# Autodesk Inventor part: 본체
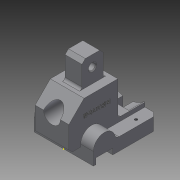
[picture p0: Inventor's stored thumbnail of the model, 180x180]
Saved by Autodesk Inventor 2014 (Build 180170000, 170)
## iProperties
Created: 2016-11
Part Number: 본체
Material: 일반
Document SubType Name: Modeling
Designer: USER
Density: 1 g/cm^3
Appearance: 기본값
Author: USER
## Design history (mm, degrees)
sketch "스케치2"
  geometry: L1 (0, 0)-(3, 0); L2 (3, 0)-(3, 7); L3 (3, 7)-(23, 7); L4 (23, 7)-(23, 0); L5 (23, 0)-(76, 0); L6 (76, 15)-(0, 15); L7 (76, 0)-(76, 15); L8 (13, 7)-(13, 15); L9 (0, 15)-(0, 0); A1 r 13 centre (13, 15) between (26, 15) and (0, 15)
  constraints: 18 end point, 4 parallel, 3 perpendicular, 2 point on circle, 2 point on line, 1 centre point, 1 coincident, 1 horizontal, 1 horizontal alignment, 1 midpoint, 1 tangent
  dimensions: "d9" = 20 distance between parallel lines of L4 L2; "d10" = 7 distance between parallel lines of L1 L3; "d11" = 15 distance between parallel lines of L1 L6; "d13" = 26 diameter of A1; "d14" = 76 distance between parallel lines of L9 L7
extrude "돌출1" new body sketch "스케치2" distance "d15" = 15; taper "d16" = 0 deg
node "작업 평면6"
  node "작업 평면5"
sketch "스케치5"
  geometry: 1 further point
sketch "스케치6"
  geometry: L1 (-60, -14)-(-12, -14); L2 (-12, -14)-(-12, 44); L3 (-12, 44)-(-60, 44); L4 (-60, 44)-(-60, -14); L5 (0, 76)-(-15, 76) reference; L6 (0, 0)-(0, 3) reference
  constraints: 8 end point, 2 parallel, 1 horizontal, 1 perpendicular
  dimensions: "d28" = 90 distance between parallel lines of L5 L1; "d29" = 60 distance between parallel lines of L4 L6; "d30" = 58 distance of L3.end L1.start; "d31" = 48 distance of L1.start L1.end
extrude "돌출3" join sketch "스케치6" stored distance "d32" = 40; taper "d33" = 0 deg
fillet "모깎기1" dims "d34" = 5
sketch "스케치7"
  geometry: L1 (0, 0)-(40, 0) reference; L2 (40, 60)-(55, 60) reference; C1 r 14.5 at (20, 18); 1 further point
  constraints: 1 centre point, 1 midpoint, 1 vertical alignment
  dimensions: "d35" = 42 distance from line of L2 C1.centre; "d36" = 29 diameter of C1
extrude "돌출4" cut sketch "스케치7" distance "d37" = 7; taper "d38" = 0 deg
sketch "스케치8"
  geometry: C1 r 14.5 at (0, 0) reference; C2 r 10 at (0, 0); 1 further point
  constraints: 1 centre point, 1 coincident
  dimensions: "d39" = 20 diameter of C2
extrude "돌출5" cut sketch "스케치8" stored distance "d40" = 7; taper "d41" = 0 deg
chamfer "모따기1" distance "d42" = 1; stored, may be unused: second distance "d43" = 2, angle "d44" = 45 deg
sketch "스케치9"
  geometry: L1 (-60, 44)-(-60, -14) reference; L2 (-60, -14)-(-12, -14) reference; L3 (-42, -14)-(-60, -14); L4 (-60, 4)-(-60, -14); L5 (-60, 4)-(-42, -14); 1 further point
  constraints: 6 end point, 2 collinear, 2 point on line
  dimensions: "d45" = 45 deg angle of L1 L5; "d46" = 18 distance from line of L4.start L2
extrude "돌출6" cut sketch "스케치9" stored distance "d47" = 7; taper "d48" = 0 deg
chamfer "모따기2" distance "d49" = 4; stored, may be unused: second distance "d50" = 2, angle "d51" = 45 deg
chamfer "모따기3" distance "d52" = 5; stored, may be unused: second distance "d53" = 2, angle "d54" = 45 deg
node "작업 평면9"
sketch "스케치13"
  geometry: L1 (-55, 0)-(-55, 15) reference; L2 (-40, 0)-(-40, 15) reference; L3 (-40, 15)-(-55, 15) reference; L4 (-40, 0)-(-55, 0) reference; L5 (15, 15)-(0, 15) reference; L6 (0, 0)-(0, 15) reference; L7 (15, 15)-(15, 0) reference; L8 (0, 0)-(15, 0) reference; L9 (15, 15)-(-55, 15); L10 (-55, 15)-(-55, 0); L11 (-55, 0)-(15, 0); L12 (15, 0)-(15, 15)
  constraints: 8 end point, 2 parallel, 1 horizontal, 1 perpendicular
extrude "돌출8" join sketch "스케치13" distance "d59" = 3; taper "d60" = 0 deg
sketch "스케치16"
  geometry: L1 (0, -5)-(-40, -5); L2 (-40, -5)-(-40, 15); L3 (-40, 15)-(0, 15); L4 (0, 15)-(0, -5); L5 (-55, 15)-(15, 15) reference; 3 further points
  constraints: 8 end point, 3 midpoint, 2 parallel, 1 coincident, 1 horizontal, 1 perpendicular, 1 vertical alignment
  dimensions: "d63" = 20 distance between parallel lines of L3 L1; "d64" = 40 distance of L1.start L1.end
extrude "돌출10" join sketch "스케치16" stored distance "d65" = 18; taper "d66" = 0 deg
sketch "스케치17"
  geometry: L1 (50, -20)-(10, -20) reference; C1 r 14.5 at (30, -42) reference; A1 r 29 centre (30, -42) between (48.894, -20) and (11.106, -20); 1 further point
  constraints: 2 point on circle, 2 point on line, 1 centre point, 1 coincident
  dimensions: "d67" = 58 diameter of A1
extrude "돌출11" cut sketch "스케치17" distance "d68" = 18; taper "d69" = 0 deg
sketch "스케치18"
  geometry: L1 (50, -20)-(48.894, -20) reference; L2 (0, 0)-(60, 0) reference; L3 (11.106, -20)-(10, -20) reference; L4 (36, -13.627)-(36, 0); L5 (24, -13.627)-(24, 0); L6 (36, 0)-(24, 0); A1 r 29 centre (30, -42) between (48.894, -20) and (11.106, -20) reference; A2 r 29 centre (30, -42) between (36, -13.627) and (24, -13.627); 2 further points
  constraints: 8 end point, 4 point on circle, 2 perpendicular, 2 point on line, 1 centre point, 1 coincident, 1 collinear, 1 concentric, 1 midpoint, 1 vertical alignment
  dimensions: "d70" = 12 distance between parallel lines of L5 L4
extrude "돌출12" cut sketch "스케치18" stored distance "d71" = 18; taper "d72" = 0 deg
fillet "모깎기2" dims "d73" = 3
node "작업 평면10"
sketch "스케치20"
  geometry: L1 (45, -11.5)-(25, -11.5); L2 (25, -11.5)-(25, 13.5); L3 (25, 13.5)-(45, 13.5); L4 (45, 13.5)-(45, -11.5); L5 (55, 21)-(15, 21) reference; L6 (55, -19)-(55, 21) reference; L7 (55, -19)-(15, -19) reference; L8 (15, 21)-(15, -19) reference; L9 (55, 21)-(15, 21) reference; L10 (55, -19)-(55, 21) reference; 5 further points
  constraints: 8 end point, 4 midpoint, 2 parallel, 1 horizontal, 1 horizontal alignment, 1 perpendicular, 1 vertical alignment
  dimensions: "d77" = 25 distance of L3.end L1.start; "d78" = 20 distance of L1.start L1.end
extrude "돌출13" join sketch "스케치20" stored distance "d79" = 18; taper "d80" = 0 deg
fillet "모깎기3" dims "d81" = 3
chamfer "모따기4" distance "d82" = 4; stored, may be unused: second distance "d83" = 2, angle "d84" = 45 deg
sketch "스케치21"
  geometry: L1 (-30, 7)-(-30, 24) reference; L2 (60, 14.5)-(60, 62.5) reference; C1 r 4 at (-17, 15.5); 2 further points
  constraints: 1 centre point, 1 horizontal alignment, 1 midpoint
  dimensions: "d85" = 8 diameter of C1; "d86" = 77 distance from line of L2 C1.centre
extrude "돌출14" cut sketch "스케치21" stored distance "d87" = 18; taper "d88" = 0 deg
chamfer "모따기5" distance "d89" = 1; stored, may be unused: second distance "d90" = 2, angle "d91" = 45 deg
chamfer "모따기6" distance "d92" = 1; stored, may be unused: second distance "d93" = 2, angle "d94" = 45 deg
sketch "스케치22"
  geometry: L1 (-23, 44)-(-60, 44) reference; L2 (-60, 44)-(-60, 4) reference; 2 further points
  constraints: 1 other
  dimensions: "d95" = 25 distance from line of L1 point (-42, 19); "d96" = 18 distance from line of L2 point (-42, 19)
extrude "돌출15" join sketch "스케치22" distance "d97" = 0.5; taper "d98" = 0 deg
sketch "스케치23"
  geometry: L1 (0, 45.708)-(10, 45.708) reference; L2 (-1.106, 27.708)-(-38.894, 27.708) reference; L3 (-20, 27.708)-(-20, 47.383); 2 further points
  constraints: 2 end point, 1 midpoint, 1 perpendicular
  dimensions: "d99" = 18 distance from line of point (7.5, 27.708) L1; "d100" = 27.5 distance from line of L3 point (7.5, 27.708)
sketch "스케치24"
  geometry: L1 (15, 45.708)-(5, 45.708) reference; L2 (53.894, 27.708)-(16.106, 27.708) reference; L3 (35, 27.708)-(35, 47.631); 2 further points
  constraints: 2 end point, 1 midpoint, 1 perpendicular
  dimensions: "d101" = 18 distance from line of L1 point (7.5, 27.708); "d102" = 27.5 distance from line of L3 point (7.5, 27.708)
hole "구멍1" sketch "스케치24" at (7.5, 27.708) diameter "d103" = 3.242; stored, may be unused: countersink angle "d107" = 90 deg, drill point angle "d109" = 118 deg; dims "d104" = 6, "d105" = 4, "d106" = 2, "d108" = 8
hole "구멍2" sketch "스케치23" diameter "d110" = 3.242; stored, may be unused: countersink angle "d114" = 90 deg, drill point angle "d116" = 118 deg; dims "d111" = 6, "d112" = 4, "d113" = 2, "d115" = 8
node "솔리드1"
mirror "대칭2"
node "투영된 루프6"
other parameters: "d58" = -3
